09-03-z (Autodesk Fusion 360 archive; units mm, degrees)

design "09-03-z" references "09-03-KOTEI", "09-03-KADOU"
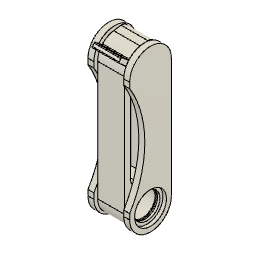
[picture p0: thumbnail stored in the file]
component_insert "コンポーネントの挿入1"
ground "固定1"
component_insert "コンポーネントの挿入3"
ground "固定4"
joint "アセンブリ" alignAngle 0 alignOffsetX 0 alignOffsetY 0 alignOffsetZ -0.5

design "09-03-KADOU"
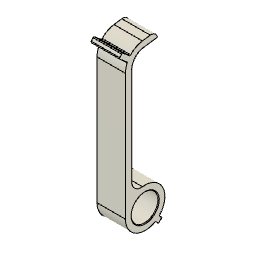
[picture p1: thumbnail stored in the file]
sketch "スケッチ1" plane through (0, 0, 0) normal (1, 0, 0) x axis (0, 0, -1)
  circle C1 centre (0, 0) radius 6.25
  point P1 (0, 0)
  point P2 (0, 0)
  coincident P1 P2
  dimension "d1" diameter C1 = 12.5
extrude "押し出し1" new body sketch "スケッチ1" distance 9
sketch "スケッチ2" plane through (0, 0, 0) normal (1, 0, 0) x axis (0, 0, -1)
  line L1 (-4.25, 0) -> (-4.25, 40)
  line L2 (-6.25, 0) -> (-4.25, 0)
  line L3 (-6.25, 40) -> (-6.25, 0)
  line L4 (3.8647, 44.8349) -> (-0.5915, 44.2086)
  line L5 (3.5864, 46.8155) -> (3.8647, 44.8349)
  line L6 (-0.8698, 46.1892) -> (3.5864, 46.8155)
  circle C1 centre (0, 0) radius 6.25
  arc A1 centre (0, 40) radius 4.25 clockwise from (-4.25, 40) to (-0.5915, 44.2086)
  arc A2 centre (0, 40) radius 6.25 clockwise from (-6.25, 40) to (-0.8698, 46.1892)
  point P1 (0, 0)
  point P8 (0, 40)
  point P12 (0, 40)
  vertical L1
  horizontal L2
  vertical L3
  coincident P1 L2
  tangent L3 C1
  perpendicular L4 L5
  perpendicular L5 L6
  coincident P8 P12
  vertical P1 P8
  tangent L1 A1
  tangent A1 L4
  tangent L3 A2
  dimension "d5" distance L1 L3 = 2
  dimension "d18" distance L4 L6 = 2
  dimension "d21" distance P8 L5 = 4.5
  dimension "d22" angle L1 L4 = 98
  dimension "d54" distance P1 P12 = 40
extrude "押し出し2" add sketch "スケッチ2" profile of L1 L3 C1 distance 9
sketch "スケッチ4" plane through (0, 0, 0) normal (1, 0, 0) x axis (0, 0, -1)
  line L1 (5.3033, -5.3033) -> (0, 0)
  line L2 (4.2426, -6.364) -> (5.3033, -5.3033)
  line L3 (-1.0607, -1.0607) -> (4.2426, -6.364)
  line L4 (0, 0) -> (-1.0607, -1.0607)
  line L5 (-22.5, 0) -> (-1.75, 0)
  point P1 (0, 0)
  point P2 (0, 0)
  perpendicular L1 L2
  parallel L1 L3
  parallel L2 L4
  coincident P1 P2
  dimension "d24" angle L1 L5 = 45
  dimension "d25" distance L2 L4 = 7.5
  dimension "d26" distance L1 L3 = 1.5
extrude "押し出し4" add sketch "スケッチ4" profile of L1 L2 L3 L4 distance 9
joint_origin "JointOrigin1" OffsetX 0 OffsetY 0 OffsetZ 0 AngleZ 0
sketch "スケッチ5" plane through (0, 0, 0) normal (1, 0, 0) x axis (0, 0, -1)
  line L1 (0, 40) -> (-7.2774, 46.1065)
  line L2 (-0.9642, 38.8509) -> (0, 40)
  line L3 (-8.2416, 44.9574) -> (-0.9642, 38.8509)
  line L4 (-7.2774, 46.1065) -> (-8.2416, 44.9574)
  line L5 (0, 22.5) -> (0, 1.75)
  arc A1 centre (0, 40) radius 4.25 clockwise from (-4.25, 40) to (-0.5915, 44.2086)
  point P3 (0, 40)
  point P8 (0, 40)
  perpendicular L1 L2
  parallel L1 L3
  parallel L2 L4
  coincident P3 P8
  dimension "d33" angle L1 L5 = 50
  dimension "d34" distance L1 L3 = 1.5
  dimension "d35" distance L2 L4 = 9.5
extrude "押し出し5" add sketch "スケッチ5" profile of L1 L3 L4 A1 distance 9
fillet "フィレット3" radius 2
sketch "スケッチ6" plane through (0, 43.4339, 6.1042) normal (0, -0.9903, -0.1392) x axis (-1, 0, 0)
  line L1 (-4.5, 10.0669) -> (4.5, 10.0669)
  line L2 (-4.5, 5.5669) -> (-4.5, 10.0669)
  line L3 (4.5, 5.5669) -> (-4.5, 5.5669)
  line L4 (4.5, 10.0669) -> (4.5, 5.5669)
  circle C1 centre (0, 8.0669) radius 0.75
  point P1 (0, 0)
  point P6 (0, 8.0669)
  vertical P1 P6
  dimension "d40" distance L1 P6 = 2
  dimension "d41" diameter C1 = 1.5
extrude "押し出し6" add sketch "スケッチ6" profile of C1 along normal blind 0.7
fillet "フィレット4" radius 0.6
fillet "フィレット5" radius 3
fillet "フィレット6" radius 0.3
hole "穴" HoleDepth 9 HoleDiameter 8.5 TipAngle 118
chamfer "面取り" distance 0.2

design "09-03-KOTEI"
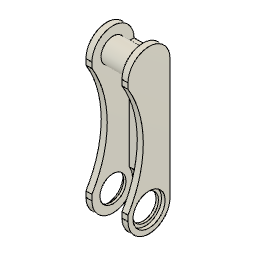
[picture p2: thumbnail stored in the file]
sketch "スケッチ1" plane through (0, 0, 0) normal (1, 0, 0) x axis (0, 0, -1)
  circle C1 centre (0, 40) radius 4
  point P1 (0, 0)
  point P2 (0, 40)
  vertical P1 P2
  dimension "d1" diameter C1 = 8
  dimension "d29" distance P1 P2 = 40
extrude "押し出し1" new body sketch "スケッチ1" + "スケッチ5" profile of S1:C1 distance 10
sketch "スケッチ2" plane through (5, 0, 0) normal (1, 0, 0) x axis (0, 0, -1)
  line L1 (-7, 0) -> (-7, 40)
  line L2 (7, 40) -> (7, 0)
  line L3 (0, 0) -> (0, 40)
  circle C1 centre (0, 40) radius 4
  arc A1 centre (0, 0) radius 7 clockwise from (7, 0) to (-7, 0)
  arc A2 centre (0, 40) radius 7 clockwise from (-7, 40) to (7, 40)
  point P7 (0, 40)
  point P9 (0, 40)
  point P8 (0, 0)
  tangent L1 A1
  tangent A1 L2
  parallel L1 L2
  tangent L2 A2
  tangent L1 A2
  vertical L3
  coincident P7 P9
  concentric C1 A2
  dimension "d4" radius A2 = 7
  dimension "d5" distance P7 P8 = 40
extrude "押し出し2" add sketch "スケッチ2" profile of C1 L1 A1 L2 A2 along normal blind 2
mirror "ミラー" sketch "スケッチ5" mirrorStitchTolerance 0.1
sketch "スケッチ3" plane through (0, 0, 0) normal (1, 0, 0) x axis (0, 0, -1)
  line L1 (7, 40) -> (5.4, 40)
  line L2 (7, 0) -> (7, 40)
  line L3 (5.4, 0) -> (7, 0)
  line L4 (5.4, 40) -> (5.4, 0)
  point P3 (7, 40)
  point P6 (7, 40)
  point P4 (7, 0)
  point P7 (7, 0)
  horizontal L1
  vertical L2
  horizontal L3
  vertical L4
  coincident P3 P6
  coincident P4 P7
  dimension "d10" distance L2 L4 = 1.6
extrude "押し出し3" add sketch "スケッチ3" distance 10
sketch "スケッチ4" plane through (0, 0, 0) normal (1, 0, 0) x axis (0, 0, -1)
  circle C1 centre (-36.9324, 20) radius 35
  arc A1 centre (0, 40) radius 7 clockwise from (-7, 40) to (7, 40)
  arc A2 centre (0, 0) radius 7 clockwise from (7, 0) to (-7, 0)
  tangent C1 A1
  tangent C1 A2
  dimension "d13" diameter C1 = 70
extrude "押し出し4" cut sketch "スケッチ4" profile of C1 no distance stored
sketch "スケッチ5" plane through (0, 0, 0) normal (1, 0, 0) x axis (0, 0, -1)
  circle C1 centre (0, 0) radius 6.5
  arc A1 centre (0, 0) radius 7 clockwise from (7, 0) to (-7, 0)
  concentric C1 A1
  dimension "d15" diameter C1 = 13
extrude "押し出し5" cut sketch "スケッチ5" profile of C1 distance 10
chamfer "面取り" distance 0.2
hole "穴1" HoleDepth 2 HoleDiameter 8.7 TipAngle 118 CBDepth 1.2 CBDiameter 10.7
hole "穴2" HoleDepth 2 HoleDiameter 8.7 TipAngle 118 CBDepth 1.2 CBDiameter 10.7
joint_origin "JointOrigin1" sketch "スケッチ5" OffsetX 0 OffsetY 0 OffsetZ 0 AngleZ 0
